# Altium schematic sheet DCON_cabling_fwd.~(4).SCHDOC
size B; Organization: Monterey Bay Aquarium Research Institute; Address1: 7700 Sandholdt Rd; Address2: Moss Landing, CA 95039-9644; CompanyName: MBARI
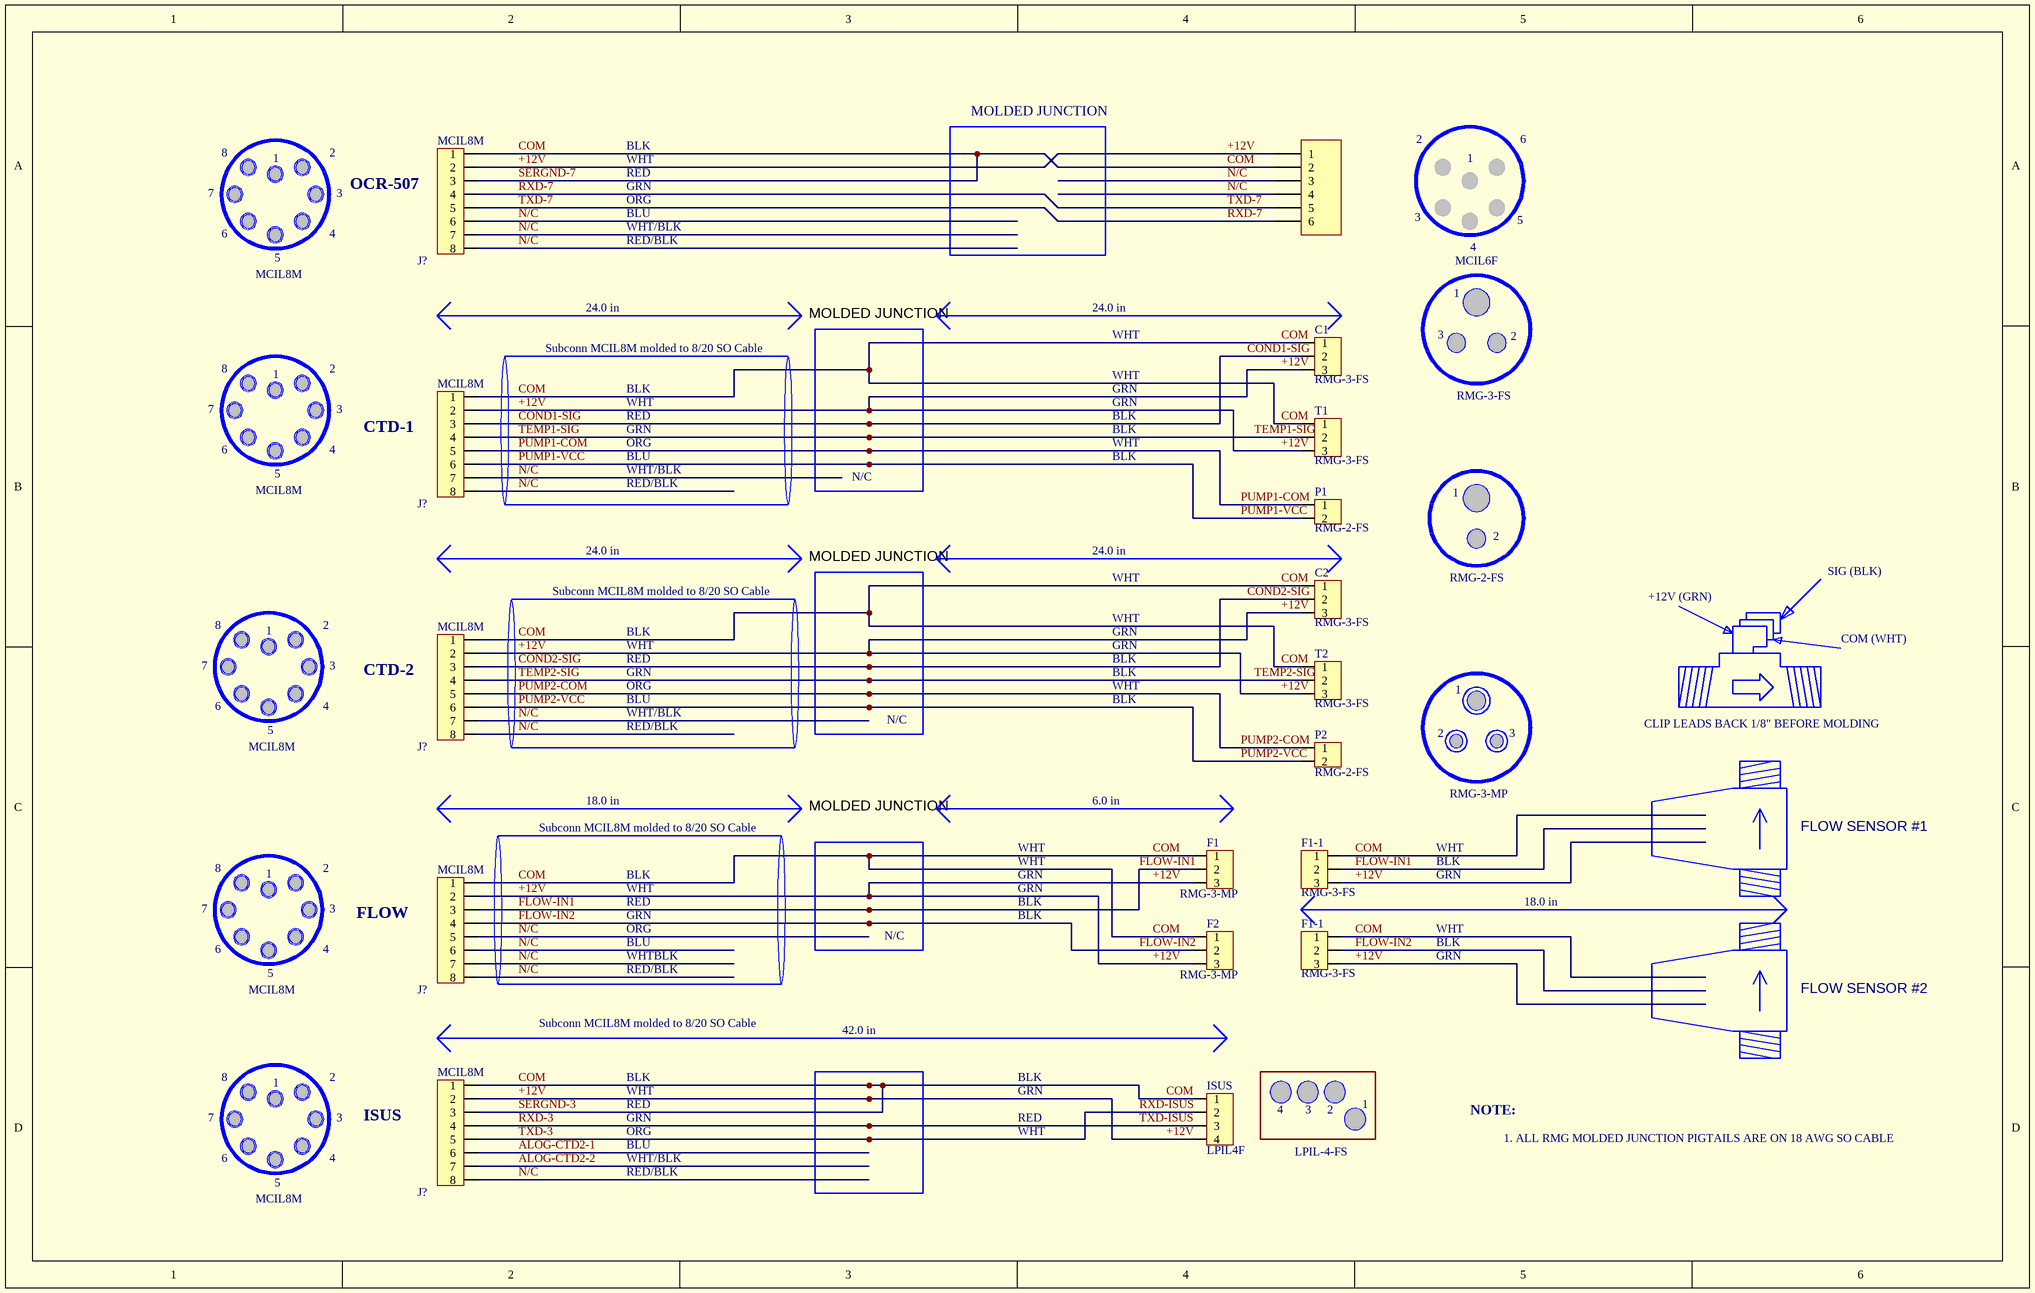
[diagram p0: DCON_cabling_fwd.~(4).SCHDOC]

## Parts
(Parts that share a designator on the sheet are numbered #1, #2 ... from top to bottom, then left to right.)
*  MCIL6F  [HDR1X6]
C1  RMG-3-FS  [SIP6]
C2  RMG-3-FS  [SIP6]
F1  RMG-3-FS  [SIP6]
F1-1#1  RMG-3-MP  [SIP6]
F1-1#2  RMG-3-MP  [SIP6]
F2  RMG-3-FS  [SIP6]
ISUS  LPIL4F  [SIP6]
J?#1  MCIL8M  [SIP8]
J?#2  MCIL8M  [SIP8]
J?#3  MCIL8M  [SIP8]
J?#4  MCIL8M  [SIP8]
J?#5  MCIL8M  [SIP8]
JP?  Header 6  [HDR1X6]  (value not drawn)
P1  RMG-2-FS  [SIP6]
P2  RMG-2-FS  [SIP6]
T1  RMG-3-FS  [SIP6]
T2  RMG-3-FS  [SIP6]

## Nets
+12V: C1.3 C2.3 F1.3 F1-1#1.3 F1-1#2.3 F2.3 ISUS.4 J?#1.2 J?#2.2 J?#3.2 J?#4.2 J?#5.2 JP?.1 T1.3 T2.3
ALOG-CTD2-1: J?#5.6
ALOG-CTD2-2: J?#5.7
COM: C1.1 C2.1 F1.1 F1-1#1.1 F1-1#2.1 F2.1 ISUS.1 J?#1.1 J?#1.3 J?#2.1 J?#3.1 J?#4.1 J?#5.1 J?#5.3 JP?.2 T1.1 T2.1  [also labelled SERGND-3, SERGND-7]
COND1-SIG: C1.2 J?#2.3
COND2-SIG: C2.2 J?#3.3
FLOW-IN1: F1.2 F1-1#1.2 J?#4.3
FLOW-IN2: F1-1#2.2 F2.2 J?#4.4
N/C: J?#1.6 J?#1.7 J?#1.8 J?#2.7 J?#2.8 J?#3.7 J?#3.8 J?#4.5 J?#4.6 J?#4.7 J?#4.8 J?#5.8 JP?.3 JP?.4
PUMP1-COM: J?#2.5 P1.1
PUMP1-VCC: J?#2.6 P1.2
PUMP2-COM: J?#3.5 P2.1
PUMP2-VCC: J?#3.6 P2.2
RXD-3: ISUS.3 J?#5.4  [also labelled TXD-ISUS]
RXD-7: J?#1.4 J?#1.5 JP?.5 JP?.6  [also labelled TXD-7]
RXD-ISUS: ISUS.2 J?#5.5  [also labelled TXD-3]
TEMP1-SIG: J?#2.4 T1.2
TEMP2-SIG: J?#3.4 T2.2

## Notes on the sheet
- 8
- 1
- 2
- BLK
- WHT
- MOLDED JUNCTION
- 7
- 6
- 4
- 3
- OCR-507
- RED
- GRN
- ORG
- BLU
- WHT/BLK
- MCIL8M
- 5
- RED/BLK
- Subconn MCIL8M molded to 8/20 SO Cable
- 24.0 in
- CTD-1
- RMG-3-FS
- N/C
- RMG-2-FS
- +12V (GRN)
- SIG (BLK)
- COM (WHT)
- CTD-2
- CLIP LEADS BACK 1/8" BEFORE MOLDING
- 18.0 in
- 6.0 in
- RMG-3-MP
- FLOW SENSOR #1
- FLOW
- WHTBLK
- 42.0 in
- FLOW SENSOR #2
- ISUS
- LPIL-4-FS
- NOTE:
- 1. ALL RMG MOLDED JUNCTION PIGTAILS ARE ON 18 AWG SO CABLE

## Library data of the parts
C1 C2 F1 F1-1#1 F1-1#2 F2 T1 T2 = CON3: Connector
ISUS = CON4: Connector
J?#1 = CON8: Connector
J?#2-J?#5 = CON8: Connector; ManufPartNo: MCIL8M molded to 24"  8/20 SO Cable; Manufacturer: Subconn
JP? = Header 6: Header, 6-Pin; Manufacturer: Generic Components; Class I: Connector
P1 P2 = CON2: Connector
